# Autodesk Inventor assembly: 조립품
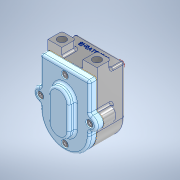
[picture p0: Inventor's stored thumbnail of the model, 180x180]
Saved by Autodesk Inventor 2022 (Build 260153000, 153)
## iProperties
Created: 2024-03
Part Number: 조립품
Document SubType Name: Assembly
Designer: PC-12
Author: PC-12
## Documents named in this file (9)
- C:\Users\PC-12\Desktop\740304V1019\조립품.iam
- C:\Users\PC-12\Desktop\740304V1019\본체.ipt
- C:\Users\PC-12\Desktop\740304V1019\커버.ipt
- C:\Users\PC-12\Desktop\740304V1019\구동기어.ipt
- C:\Users\PC-12\Desktop\740304V1019\스퍼기어.ipt
- C:\Users\PC-12\Desktop\740304V1019\오일레스 부시.ipt
- C:\Users\PC-12\Desktop\740304V1019\가스켓.ipt
- C:\Users\PC-12\Desktop\740304V1019\오일 실 14 25 7.ipt
- C:\Users\PC-12\Desktop\740304V1019\육각 소켓 머리 볼트 M5x12.ipt
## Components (2 placed, 2 different names)
1. 구동기어:1
2. 가스켓:1
